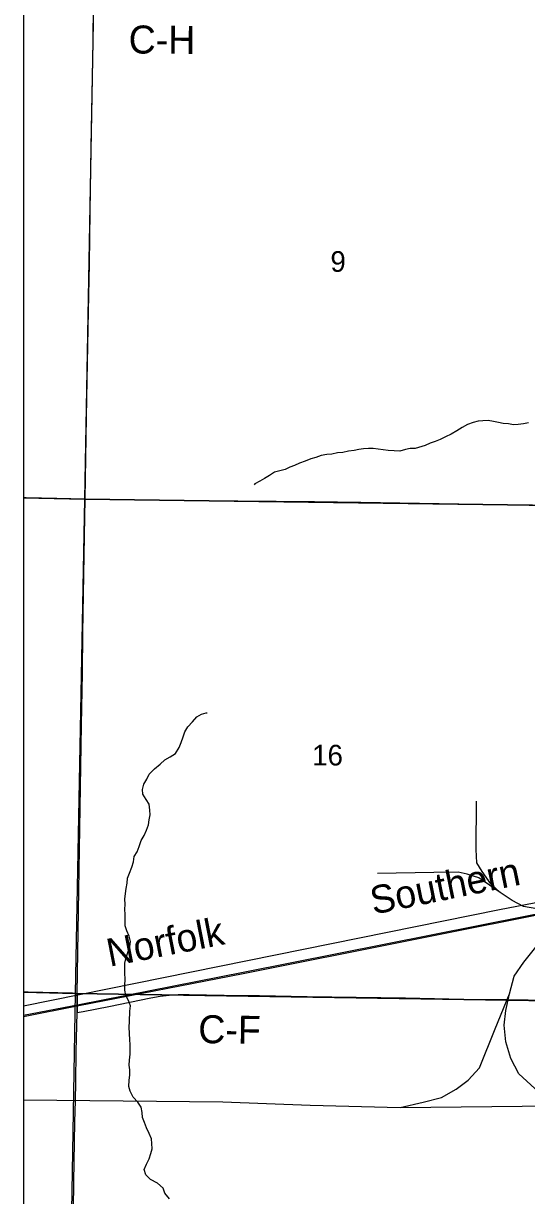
# Model space of a CAD drawing. Extents: x 0 to 42, y 0 to 22.
# Drawn here: x 2.1 to 3.119, y 16.093 to 18.47 of the extents above; entities that cross this region are included whole.
import ezdxf

# ---------------------------------------------------------------- set-up
doc = ezdxf.new("R2010")
doc.units = 0
for name, color, linetype in [('Default', 7, 'Continuous'), ('GM_X_County_Road', 7, 'Continuous'), ('GM_X_County_Road_Text', 7, 'Continuous'), ('GM_X_Interchange_Ramps', 7, 'Continuous'), ('GM_X_Minor_River', 7, 'Continuous'), ('GM_X_Rail_Line', 7, 'Continuous'), ('GM_X_Rail_Line_Text', 7, 'Continuous'), ('GM_X_Section', 7, 'Continuous'), ('GM_X_Section_Text', 7, 'Continuous'), ('GM_X_State_Route', 7, 'Continuous'), ('GM_X_Township_Road', 7, 'Continuous'), ('GM_X_US_Route', 7, 'Continuous')]:
    doc.layers.add(name, color=color, linetype=linetype)

msp = doc.modelspace()

# ---------------------------------------------------------------- linework, layer by layer
at = {"layer": 'Default'}
for points in [[(2.1, 18.5124), (2.1, 17.5078), (2.2245, 17.5054), (2.2423, 18.509)], [(2.1, 17.5078), (2.1, 16.5057), (2.2056, 16.5033), (2.2245, 17.5054)], [(2.1, 16.5057), (2.1, 15.5023), (2.1886, 15.5005), (2.2056, 16.5033)]]:
    msp.add_lwpolyline(points, close=True, dxfattribs=at)
at = {"layer": 'GM_X_County_Road'}
for points in [[(2.2251, 17.5061), (2.2279, 17.6719), (2.229, 17.7465), (2.2316, 17.8864), (2.2335, 17.9827), (2.2355, 18.0884), (2.2374, 18.2189), (2.241, 18.4334), (2.242, 18.5088)], [(2.2088, 16.5033), (2.2176, 17.0472), (2.2193, 17.1529), (2.2205, 17.2337), (2.2245, 17.4699), (2.2251, 17.5041), (2.2251, 17.5061)], [(2.1, 16.5069), (2.1095, 16.5066), (2.1997, 16.5046), (2.2088, 16.5033)], [(2.209, 16.4644), (2.209, 16.466), (2.2088, 16.5033)], [(2.209, 16.4644), (2.2212, 16.4668), (2.2731, 16.4767), (2.3584, 16.4941), (2.3767, 16.4974), (2.389, 16.499), (2.4013, 16.5001), (2.4137, 16.5007), (2.4355, 16.5009), (2.507, 16.4998), (2.5785, 16.4988), (2.6748, 16.4969), (2.8738, 16.4939), (2.9919, 16.4918), (3.0632, 16.491), (3.0779, 16.4906), (3.1679, 16.4894), (3.2134, 16.4891)], [(2.1907, 15.5024), (2.1914, 15.5243), (2.1926, 15.5989), (2.1946, 15.7077), (2.1992, 15.9595), (2.2004, 16.0154), (2.2015, 16.0651), (2.2023, 16.1211), (2.2044, 16.2423), (2.2053, 16.2858), (2.206, 16.3231), (2.2069, 16.3852), (2.2082, 16.4381), (2.209, 16.4644)]]:
    msp.add_lwpolyline(points, dxfattribs=at)
at = {"layer": 'GM_X_Interchange_Ramps'}
msp.add_lwpolyline([(2.1, 18.5138), (2.1, 14.1)], dxfattribs=at)
at = {"layer": 'GM_X_Minor_River'}
for points in [[(3.1232, 17.6602), (3.1133, 17.6581), (3.1026, 17.6565), (3.0927, 17.6563), (3.0825, 17.658), (3.0723, 17.6587), (3.0625, 17.6608), (3.0527, 17.6625), (3.0417, 17.6646), (3.0311, 17.6645), (3.0212, 17.6636), (3.0113, 17.6611), (2.9994, 17.6565), (2.9886, 17.6506), (2.9779, 17.6441), (2.9663, 17.6371), (2.9552, 17.632), (2.9441, 17.6266), (2.9345, 17.6226), (2.9242, 17.6191), (2.9138, 17.614), (2.8939, 17.6084), (2.8837, 17.6078), (2.8742, 17.6058), (2.8623, 17.6026), (2.8513, 17.6036), (2.8392, 17.6043), (2.8286, 17.6053), (2.8184, 17.6066), (2.8086, 17.608), (2.7991, 17.6078), (2.7892, 17.6076), (2.7797, 17.606), (2.7698, 17.6043), (2.7584, 17.6026), (2.7473, 17.6002), (2.7366, 17.599), (2.7248, 17.5969), (2.7146, 17.5956), (2.7031, 17.5936), (2.6924, 17.5897), (2.6825, 17.5873), (2.671, 17.5826), (2.6591, 17.5783), (2.6495, 17.5736), (2.6396, 17.5704), (2.63, 17.5656), (2.6197, 17.5628), (2.609, 17.56), (2.5986, 17.5534), (2.5886, 17.5472), (2.579, 17.5417), (2.5686, 17.5367), (2.5674, 17.5344)], [(2.306, 16.6404), (2.306, 16.6529), (2.3058, 16.6639), (2.3057, 16.6734), (2.3063, 16.684), (2.3054, 16.6943), (2.3068, 16.706), (2.3082, 16.7159), (2.31, 16.7268), (2.3106, 16.7371), (2.315, 16.7472), (2.3194, 16.7593), (2.3227, 16.7702), (2.3245, 16.7808), (2.3304, 16.7905), (2.3345, 16.8011), (2.3385, 16.8131), (2.3448, 16.8232), (2.3496, 16.8345), (2.3533, 16.845), (2.3547, 16.8549), (2.3568, 16.8654), (2.3559, 16.875), (2.3547, 16.8867), (2.3488, 16.8967), (2.3422, 16.9071), (2.3409, 16.9167), (2.3438, 16.9272), (2.3502, 16.9377), (2.3549, 16.9475), (2.3654, 16.9586), (2.3767, 16.9682), (2.3867, 16.9767), (2.3971, 16.9826), (2.4079, 16.9899), (2.4154, 17.0019), (2.4198, 17.0117), (2.4235, 17.0234), (2.4267, 17.0335), (2.4331, 17.0436), (2.4424, 17.0541), (2.451, 17.0637), (2.461, 17.0692), (2.4705, 17.0724), (2.4724, 17.072)], [(2.396, 16.0869), (2.3867, 16.0981), (2.3828, 16.1085), (2.3717, 16.1186), (2.3574, 16.1258), (2.3478, 16.1351), (2.3446, 16.1462), (2.3494, 16.1571), (2.3546, 16.1676), (2.3579, 16.1785), (2.3608, 16.1883), (2.3603, 16.1986), (2.3597, 16.2081), (2.3547, 16.2192), (2.3492, 16.2307), (2.3453, 16.2414), (2.3414, 16.2517), (2.3405, 16.2616), (2.3385, 16.2727), (2.3319, 16.2827), (2.3226, 16.2928), (2.3161, 16.3051), (2.3136, 16.3146), (2.3143, 16.3271), (2.3153, 16.3377), (2.3156, 16.3483), (2.3143, 16.3579), (2.3149, 16.3681), (2.3163, 16.3798), (2.3161, 16.3893), (2.3164, 16.3995), (2.3155, 16.4091), (2.3146, 16.422), (2.3145, 16.4345), (2.3152, 16.4463), (2.3157, 16.4675), (2.3167, 16.4781), (2.3131, 16.4888), (2.3073, 16.4988), (2.3057, 16.5098), (2.3055, 16.5193), (2.3058, 16.5322), (2.3057, 16.5444), (2.3052, 16.5546), (2.3054, 16.5645), (2.3083, 16.5758), (2.3112, 16.586), (2.3153, 16.5981), (2.3167, 16.6087), (2.3143, 16.619), (2.3096, 16.6304), (2.306, 16.6404)]]:
    msp.add_lwpolyline(points, dxfattribs=at)
at = {"layer": 'GM_X_Rail_Line'}
msp.add_line((2.8633, 16.272), (3.2142, 16.2756), dxfattribs=at)
for points in [[(2.1, 16.459), (2.2129, 16.4808), (2.5454, 16.5465), (3.2154, 16.6797), (3.8608, 16.8081), (4.4734, 16.9293), (4.9678, 17.0293), (5.6609, 17.1675), (6.33, 17.2984), (6.9548, 17.4275), (7.5722, 17.5495), (8.2054, 17.6814), (8.8625, 17.8098), (8.9, 17.8172)], [(2.1, 16.4567), (2.2123, 16.4784), (2.5452, 16.5433), (3.215, 16.6775), (3.8612, 16.8058), (4.4739, 16.927), (4.9682, 17.0271), (5.6614, 17.1653), (6.3305, 17.2961), (6.9553, 17.4252), (7.5727, 17.5472), (8.2058, 17.6791), (8.8629, 17.8076), (8.9, 17.8149)], [(2.1, 16.4779), (3.0648, 16.6733), (4.4738, 16.9443)], [(3.0656, 16.708), (3.0467, 16.7252), (3.0294, 16.7507), (3.0187, 16.768), (3.0171, 16.7951), (3.0179, 16.8929)], [(3.0656, 16.708), (3.0228, 16.7376), (2.999, 16.745), (2.9809, 16.7491), (2.9316, 16.7482), (2.8173, 16.7466)], [(3.1894, 16.6814), (3.1399, 16.6744), (3.1133, 16.6792), (3.0903, 16.6915), (3.0656, 16.708)], [(3.0848, 16.502), (3.0944, 16.538), (3.1136, 16.5667), (3.1411, 16.6003), (3.1771, 16.6255), (3.2266, 16.6448)], [(2.8633, 16.272), (2.91, 16.2828), (2.9471, 16.2924), (2.977, 16.3091), (3.001, 16.3271), (3.0238, 16.3523), (3.0561, 16.4314), (3.0848, 16.502)], [(3.2142, 16.2756), (3.1639, 16.29), (3.1363, 16.3103), (3.104, 16.3403), (3.0872, 16.3714), (3.0777, 16.405), (3.0741, 16.4385), (3.0777, 16.4685), (3.0848, 16.502)], [(2.1, 16.2873), (2.5038, 16.2834), (2.6812, 16.2768), (2.8633, 16.272)]]:
    msp.add_lwpolyline(points, dxfattribs=at)
at = {"layer": 'GM_X_Section'}
for points in [[(2.2423, 18.509), (3.2549, 18.4906), (3.2323, 17.4917), (2.2245, 17.5054)], [(3.2323, 17.4917), (3.2111, 16.4878), (2.2056, 16.5033), (2.2245, 17.5054)], [(2.2056, 16.5033), (3.2111, 16.4878), (3.1895, 15.4854), (2.1886, 15.5005)]]:
    msp.add_lwpolyline(points, close=True, dxfattribs=at)
at = {"layer": 'GM_X_State_Route'}
for points in [[(2.1, 17.5085), (2.1055, 17.5084), (2.1677, 17.5072), (2.2251, 17.5061)], [(2.2251, 17.5061), (2.2983, 17.5048), (2.3418, 17.5042), (2.4755, 17.5029), (2.5346, 17.5023), (2.69, 17.5004), (2.7833, 17.499), (3.0614, 17.4943)], [(3.0614, 17.4943), (3.0934, 17.4938), (3.1555, 17.4924), (3.2306, 17.4912)]]:
    msp.add_lwpolyline(points, dxfattribs=at)
at = {"layer": 'GM_X_Township_Road'}
for points in [[(2.1, 16.5069), (2.1095, 16.5066), (2.1997, 16.5046), (2.2088, 16.5033)], [(2.2088, 16.5033), (2.209, 16.466), (2.209, 16.4644)], [(2.209, 16.4644), (2.2212, 16.4668), (2.2731, 16.4767), (2.3584, 16.4941), (2.3767, 16.4974), (2.389, 16.499), (2.4013, 16.5001), (2.4137, 16.5007), (2.4355, 16.5009), (2.507, 16.4998), (2.5785, 16.4988), (2.6748, 16.4969), (2.8738, 16.4939), (2.9919, 16.4918), (3.0632, 16.491), (3.0779, 16.4906), (3.1679, 16.4894), (3.2134, 16.4891)]]:
    msp.add_lwpolyline(points, dxfattribs=at)
at = {"layer": 'GM_X_US_Route'}
for points in [[(2.1, 17.5085), (2.1055, 17.5084), (2.1677, 17.5072), (2.2251, 17.5061)], [(2.2251, 17.5061), (2.2983, 17.5048), (2.3418, 17.5042), (2.4755, 17.5029), (2.5346, 17.5023), (2.69, 17.5004), (2.7833, 17.499), (3.0614, 17.4943)], [(3.0614, 17.4943), (3.0934, 17.4938), (3.1555, 17.4924), (3.2306, 17.4912)]]:
    msp.add_lwpolyline(points, dxfattribs=at)

# ---------------------------------------------------------------- texts
at = {"layer": 'GM_X_County_Road_Text'}
for s, rotation, p in [('C-H', 359.6023, (2.313, 18.4091)), ('C-F', 359.1191, (2.4539, 16.4025))]:
    msp.add_text(s, height=0.05682, rotation=rotation, dxfattribs=at).set_placement(p)
at = {"layer": 'GM_X_Rail_Line_Text'}
for s, rotation, p in [('Southern', 11.5058, (2.809, 16.6628)), ('Norfolk', 11.0557, (2.2746, 16.5571))]:
    msp.add_text(s, height=0.05663, rotation=rotation, dxfattribs=at).set_placement(p)
at = {"layer": 'GM_X_Section_Text'}
for s, height, p in [('9', 0.0419, (2.722, 17.9663)), ('16', 0.04186, (2.685, 16.9654))]:
    msp.add_text(s, height=height, rotation=0, dxfattribs=at).set_placement(p)

doc.saveas('drawing.dxf')
